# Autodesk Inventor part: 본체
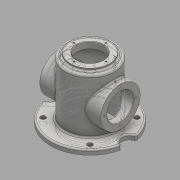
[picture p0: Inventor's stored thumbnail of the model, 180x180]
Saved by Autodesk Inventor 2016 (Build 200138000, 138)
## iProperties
Created: 2018-04
Part Number: 본체
Material: 일반
Document SubType Name: Modeling
Designer: 605-08
Density: 1 g/cm^3
Appearance: 기본값
Mass: 424.833 g
Surface Area: 1200.36 cm^2
Volume: 424.833 cm^3
Author: 605-08
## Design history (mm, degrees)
sketch "스케치1"
  geometry: C1 r 50 at (0, 0); 1 further point
  constraints: 1 centre point, 1 coincident
  dimensions: "d0" = 100 diameter of C1
extrude "돌출1" new body sketch "스케치1" distance "d1" = 8; taper "d2" = 0 deg
sketch "스케치2"
  geometry: A1 r 15 centre (-80, 0) between (-78.594, -14.934) and (-78.594, 14.934); A2 r 15 centre (80, 0) between (78.594, 14.934) and (78.594, -14.934); A3 r 80 centre (0, 0) between (-78.594, -14.934) and (78.594, -14.934); A4 r 80 centre (0, 0) between (78.594, 14.934) and (-78.594, 14.934); 1 further point
  constraints: 8 point on circle, 4 centre point, 1 coincident
  dimensions: "d4" = 30 diameter of A1; "d5" = 30 diameter of A2
extrude "돌출2" join sketch "스케치2" distance "d6" = 10; taper "d7" = 0 deg
sketch "스케치3"
  geometry: C1 r 50 at (0, 0); 1 further point
  constraints: 1 centre point, 1 coincident
  dimensions: "d8" = 100 diameter of C1
extrude "돌출3" join sketch "스케치3" distance "d9" = 110; taper "d10" = 0 deg
sketch "스케치4"
  geometry: C1 r 40 at (0, 0); 1 further point
  constraints: 1 centre point, 1 coincident
  dimensions: "d11" = 80 diameter of C1
extrude "돌출4" join sketch "스케치4" distance "d12" = 5; taper "d13" = 0 deg
sketch "스케치5" dims "d14" = 135
  geometry: L1 (0, 0)-(-80, 0); L2 (0, 0)-(-47.73, 47.73); C1 r 50 at (0, 0) reference; A1 r 15 centre (-80, 0) between (-78.594, -14.934) and (-78.594, 14.934) reference; A2 r 80 centre (0, 0) between (78.594, 14.934) and (-78.594, 14.934) reference; A3 r 15 centre (80, 0) between (78.594, 14.934) and (78.594, -14.934) reference; A4 r 80 centre (0, 0) between (-78.594, -14.934) and (78.594, -14.934) reference; 1 further point
  constraints: 4 end point, 1 coincident, 1 horizontal, 3 other
  dimensions: "d16" = 45 deg angle of L1 L2
hole "구멍1" sketch "스케치5" at (-47.73, 47.73) diameter "d17" = 10; stored, may be unused: countersink angle "d21" = 90 deg, drill point angle "d23" = 118 deg; dims "d18" = 6, "d19" = 4, "d20" = 2, "d22" = 8
sketch "스케치6"
  geometry: L1 (-50, 0)-(50, 0) reference; L2 (0, 0)-(0, 132.481); L3 (80, 8)-(14.934, 8) reference; C1 r 40 at (0, 68); 1 further point
  constraints: 2 end point, 2 vertical alignment, 1 centre point, 1 midpoint, 1 vertical
  dimensions: "d27" = 80 diameter of C1; "d29" = 60 distance from line of C1.centre L3
extrude "돌출5" join sketch "스케치6" stored distance "d30" = 124; taper "d31" = 0 deg
sketch "스케치7"
  geometry: C1 r 45 at (0, 0); 1 further point
  constraints: 1 centre point, 1 coincident
  dimensions: "d32" = 90 diameter of C1
extrude "돌출6" cut sketch "스케치7" distance "d33" = 120; taper "d34" = 0 deg
sketch "스케치8"
  geometry: C1 r 27 at (0, 0); 1 further point
  constraints: 1 centre point, 1 coincident
  dimensions: "d35" = 54 diameter of C1
extrude "돌출7" cut sketch "스케치8" stored distance "d36" = 120; taper "d37" = 0 deg
sketch "스케치9"
  geometry: C1 r 40 at (0, 0) reference; C2 r 27 at (0, 0); 1 further point
  constraints: 1 centre point, 1 coincident
  dimensions: "d38" = 54 diameter of C2
extrude "돌출8" cut sketch "스케치9" stored distance "d39" = 120; taper "d40" = 0 deg
sketch "스케치10"
  geometry: L1 (0, 0)-(-32.5, 0); C1 r 40 at (0, 0) reference; 1 further point
  constraints: 2 end point, 1 horizontal
  dimensions: "d41" = 32.5 distance of L1.start L1.end
hole "구멍2" sketch "스케치10" at (-32.5, 0) diameter "d42" = 3.242; stored, may be unused: countersink angle "d46" = 90 deg, drill point angle "d48" = 118 deg; dims "d43" = 8, "d44" = 4, "d45" = 2, "d47" = 10
sketch "스케치11"
  geometry: L1 (0, 0)-(0, 32.5); C1 r 40 at (0, 0) reference; 1 further point
  constraints: 2 end point, 1 vertical
  dimensions: "d52" = 32.5 distance of L1.start L1.end
hole "구멍3" sketch "스케치11" at (0, 32.5) diameter "d53" = 3.242; stored, may be unused: countersink angle "d57" = 90 deg, drill point angle "d59" = 118 deg; dims "d54" = 8, "d55" = 4, "d56" = 2, "d58" = 10
fillet "모깎기1" dims "d63" = 5
fillet "모깎기2" dims "d64" = 3
chamfer "모따기1" distance "d65" = 1; stored, may be unused: second distance "d66" = 2, angle "d67" = 45 deg
fillet "모깎기3" dims "d68" = 3
node "작업 평면1"
sketch "스케치12"
  geometry: L1 (78.594, 8)-(-78.594, 8) reference; 2 further points
  constraints: 1 vertical alignment, 1 other
  dimensions: "d70" = 70 distance from line of L1 point (0, 78)
feature "엠보싱1" sketch "스케치12" dims "d71" = 0.5, "d72" = 0
node "솔리드1"
pattern_circular "원형 패턴1" dims angle "d25" = 360 deg
pattern_circular "원형 패턴2" dims angle "d50" = 360 deg
mirror "대칭1"
pattern_circular "원형 패턴3" dims angle "d61" = 360 deg
node "투영된 루프1"
node "투영된 루프2"
other parameters: "d69" = 65.25
